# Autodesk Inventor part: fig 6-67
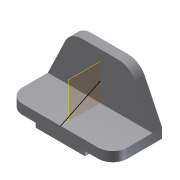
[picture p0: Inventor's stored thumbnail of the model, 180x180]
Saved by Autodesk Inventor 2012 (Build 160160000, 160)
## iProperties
Shininess: 77.0
Length Units: 11269
Angle Units: 11279
Time Units: 11290
Mass Units: 11283
Length Display Precision: 3
Angle Display Precision: 2
Created: 2001-12
Part Number: fig 6-67
Document SubType Name: Modeling
Designer: Renu Muthoo
Density: 1 g/cm^3
Material: Default
Density: 0.0
Volumn: 0.0
Area: 0.0
PropertySet Name: Model Information
Control State: 0
Master: False
Checked Out: False
Author: Renu Muthoo
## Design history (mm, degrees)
node "Sketch1"
sketch "Sketch2"
  geometry: L1 (-67.219, 19.116)-(148.781, 19.116); L2 (148.781, 19.116)-(148.781, -0.884); L3 (-67.219, -0.884)-(-67.219, 19.116); L4 (-10.219, -0.884)-(-10.219, -9.884); L5 (-10.219, -9.884)-(91.781, -9.884); L6 (91.781, -9.884)-(91.781, -0.884); L7 (148.781, -0.884)-(91.781, -0.884); L8 (-10.219, -0.884)-(-67.219, -0.884)
  constraints: 16 end point, 5 parallel, 4 perpendicular, 2 equal length, 1 horizontal
  dimensions: "d0" = 102 distance of L4.end L5.end; "d1" = 57 distance of L4.start L3.start; "d2" = 29 distance between parallel lines of L1 L5; "d3" = 20 distance of L1.end L2.end
extrude "Extrusion1" new body sketch "Sketch2" distance "d4" = 102; taper "d5" = 0 deg
sketch "Sketch3"
  geometry: L1 (67.219, -19.116)-(-148.781, -19.116) reference; L2 (67.219, -19.116)-(31.475, -93.564); L3 (-2.781, -115.116)-(-78.781, -115.116); L4 (-113.038, -93.564)-(-148.781, -19.116); A1 r 38 centre (-2.781, -77.116) between (-2.781, -115.116) and (31.475, -93.564); A2 r 38 centre (-78.781, -77.116) between (-113.038, -93.564) and (-78.781, -115.116)
  constraints: 6 end point, 4 point on circle, 4 tangent, 2 centre point, 1 equal length, 1 equal radius, 1 parallel
  dimensions: "d6" = 96 distance between parallel lines of L3 L1; "d7" = 38 radius of A1; "d8" = 76 distance of A2.centre A1.centre
extrude "Extrusion2" join sketch "Sketch3" distance "d9" = 20; taper "d10" = 0 deg
fillet "Fillet1" dims "d11" = 30
workplane "Work Plane1"
sketch "Sketch7"
  geometry: L1 (0, -82)-(-39.557, 0)
  constraints: 2 end point
body "Solid1"
other parameters: "d12" = -108
